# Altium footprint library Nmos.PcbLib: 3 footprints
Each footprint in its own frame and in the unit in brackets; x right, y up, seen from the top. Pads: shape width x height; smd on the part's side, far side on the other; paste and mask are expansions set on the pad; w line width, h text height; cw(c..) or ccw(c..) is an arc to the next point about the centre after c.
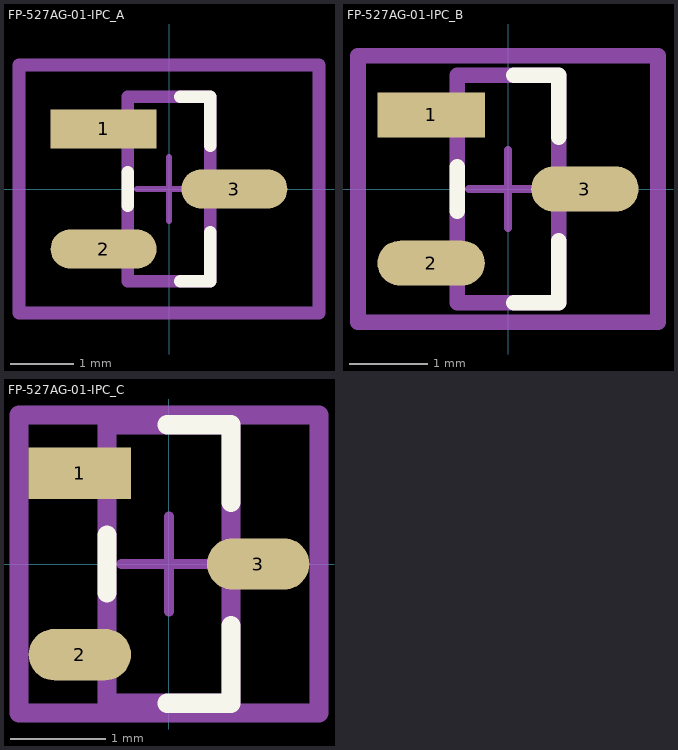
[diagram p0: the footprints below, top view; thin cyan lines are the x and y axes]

## FP-527AG-01-IPC_A [mm]
pads (3):
  rect 1.675x0.618 smd paste+0 mask+0: 1(-1.035,0.95)
  rrect100% 1.675x0.618 smd paste+0 mask+0: 2(-1.035,-0.95) 3(1.035,0)
Top Overlay:
  lines w0.2: -0.65,-0.266 -0.65,0.266 ; 0.177,-1.46 0.65,-1.46 0.65,-0.684 ; 0.177,1.46 0.65,1.46 0.65,0.684
Top Assembly:
  lines w0.2: -2.372,-1.96 2.372,-1.96 2.372,1.96 -2.372,1.96 -2.372,-1.96
  text ".Designator" at 0,-0.001 h1
Top 3D Body:
  lines w0.2: -0.65,-1.46 0.65,-1.46 0.65,1.46 -0.65,1.46 -0.65,-1.46
Top Courtyard:
  lines w0.2: -2.372,-1.96 2.372,-1.96 2.372,1.96 -2.372,1.96 -2.372,-1.96
Top Component Center:
  lines w0.1: -0.5,0 0.5,0 ; 0,-0.5 0,0.5
3D body "Trans_ON_Semiconductor_NDS355AN_eec.STEP": height 0.25, standoff 0, extent -2.372,-1.96 2.372,1.96

## FP-527AG-01-IPC_B [mm]
pads (3):
  rect 1.375x0.578 smd paste+0 mask+0: 1(-0.985,0.95)
  rrect100% 1.375x0.578 smd paste+0 mask+0: 2(-0.985,-0.95) 3(0.985,0)
Top Overlay:
  lines w0.2: -0.65,-0.286 -0.65,0.286 ; 0.077,-1.46 0.65,-1.46 0.65,-0.664 ; 0.077,1.46 0.65,1.46 0.65,0.664
Top Assembly:
  lines w0.2: -1.922,-1.71 1.922,-1.71 1.922,1.71 -1.922,1.71 -1.922,-1.71
  text ".Designator" at 0,-0.001 h1
Top 3D Body:
  lines w0.2: -0.65,-1.46 0.65,-1.46 0.65,1.46 -0.65,1.46 -0.65,-1.46
Top Courtyard:
  lines w0.2: -1.922,-1.71 1.922,-1.71 1.922,1.71 -1.922,1.71 -1.922,-1.71
Top Component Center:
  lines w0.1: -0.5,0 0.5,0 ; 0,-0.5 0,0.5
3D body "Trans_ON_Semiconductor_NDS355AN_eec.STEP": height 0.25, standoff 0, extent -1.922,-1.71 1.922,1.71

## FP-527AG-01-IPC_C [mm]
pads (3):
  rect 1.075x0.538 smd paste+0 mask+0: 1(-0.935,0.95)
  rrect100% 1.075x0.538 smd paste+0 mask+0: 2(-0.935,-0.95) 3(0.935,0)
Top Overlay:
  lines w0.2: -0.65,-0.306 -0.65,0.306 ; -0.023,-1.46 0.65,-1.46 0.65,-0.644 ; -0.023,1.46 0.65,1.46 0.65,0.644
Top Assembly:
  lines w0.2: -1.572,-1.56 1.572,-1.56 1.572,1.56 -1.572,1.56 -1.572,-1.56
  text ".Designator" at 0,-0.001 h1
Top 3D Body:
  lines w0.2: -0.65,-1.46 0.65,-1.46 0.65,1.46 -0.65,1.46 -0.65,-1.46
Top Courtyard:
  lines w0.2: -1.572,-1.56 1.572,-1.56 1.572,1.56 -1.572,1.56 -1.572,-1.56
Top Component Center:
  lines w0.1: -0.5,0 0.5,0 ; 0,-0.5 0,0.5
3D body "Trans_ON_Semiconductor_NDS355AN_eec.STEP": height 0.25, standoff 0, extent -1.572,-1.56 1.572,1.56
